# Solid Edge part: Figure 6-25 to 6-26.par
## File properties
Author: CADCIM
Template: Normal.par
Last saved by: Ashutosh-CADCIM
Revision: 5
Application: Solid Edge
Accuracy: 0.99
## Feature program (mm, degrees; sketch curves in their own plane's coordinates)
sketch for "unnamed Protrusion 1" plane through (0, 0, 0) normal (0, -1, 0) x-axis (1, 0, 0)
  line (-47.9688, 46.8859) -> (-47.9688, 0)
  line (-47.9688, 0) -> (40.7735, 0)
  line (40.7735, 0) -> (-11.0972, 46.8859)
  line (-11.0972, 46.8859) -> (-47.9688, 46.8859)
extrude "unnamed Protrusion 1" add finite 57.15 symmetric
sketch for "ExtrudedProtrusion_3" plane through (16.4336, 0, 22.0008) normal (0.670562, 0, 0.741854) x-axis (0, 1, 0)
  circle centre (0, 0.7308) radius 21.6522
extrude "ExtrudedProtrusion_3" add finite 41.275 along +normal
fillet "Round_6" radius 20
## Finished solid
Body 1: solid body, 19 faces, 41 edges, 24 vertices.
  Faces by surface: plane 10, blend 4, torus 4, cylinder 1
  Edges by curve: line 20, circle 17, intersection 4
Bounding box of the edges (mm; curved faces can reach further): 107.600 x 57.150 x 67.630, from (-47.9688, -28.575, 0) to (59.6317, 28.575, 67.63).
Cylindrical faces by radius (mm): R21.6522 x1
Toroidal faces (ring radius, tube radius in mm): R41.6522 r20 x4
Planar faces by outward normal: +y 1, +z 1, -x 1, -y 1, -z 1, oblique 5
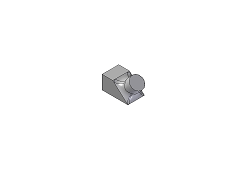
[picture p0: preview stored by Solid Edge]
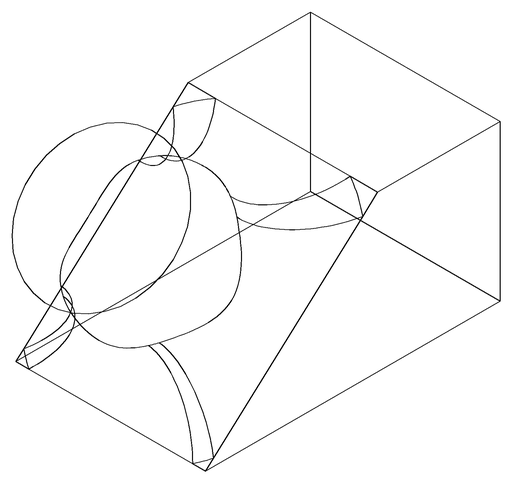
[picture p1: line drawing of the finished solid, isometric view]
